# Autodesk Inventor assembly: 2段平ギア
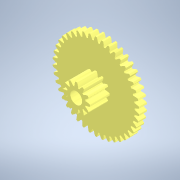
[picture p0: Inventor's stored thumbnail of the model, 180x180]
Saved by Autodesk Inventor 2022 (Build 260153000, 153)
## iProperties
Created: 2024-11
Part Number: 2段平ギア
Document SubType Name: Assembly
Designer: neo09
Author: neo09
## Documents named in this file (3)
- C:\Users\jsat7\OneDrive\デスクトップ\卒論2024\３DCAD\自在ギヤボックス\部品図\2段平ギア.iam
- C:\Users\jsat7\OneDrive\デスクトップ\卒論2024\３DCAD\自在ギヤボックス\部品図\42Tギア.ipt
- C:\Users\jsat7\OneDrive\デスクトップ\卒論2024\３DCAD\自在ギヤボックス\部品図\12Tギア　平ギア.ipt
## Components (2 placed, 1 different names)
1. 平歯車1:1 — リジッド:1
2. 平歯車1:2 — リジッド:1
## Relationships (1: WeldJoint 1)
- リジッド:1 [WeldJoint]: 平歯車1:1 ↔ 平歯車1:2
